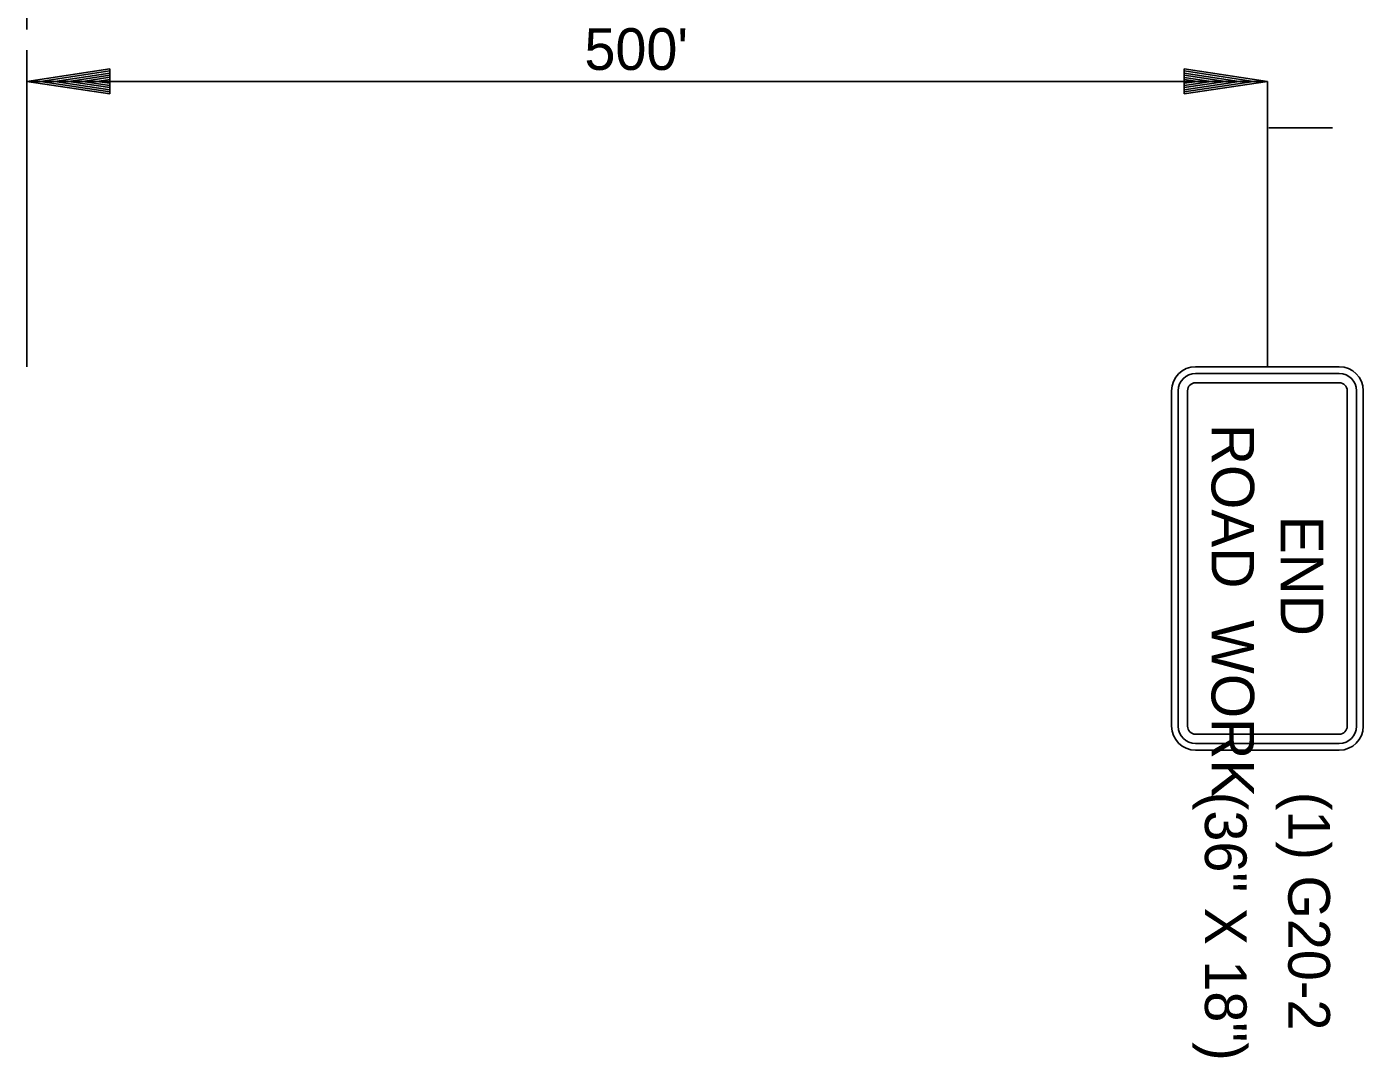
# Model space of a CAD drawing. Extents: x 913 to 1207, y 319 to 519.
# Drawn here: x 1075.27 to 1113.75, y 382.61 to 412.28 of the extents above; entities that cross this region are included whole.
import ezdxf

# ---------------------------------------------------------------- set-up
doc = ezdxf.new("R2010")
doc.units = 0
doc.layers.add('R_Annotation', color=7, linetype='Continuous')
doc.layers.add('R_Draft', color=7, linetype='Continuous')

msp = doc.modelspace()

# ---------------------------------------------------------------- linework, layer by layer
at = {"layer": 'R_Annotation'}
for p, q in [((1113.059, 402.488), (1108.921, 402.488)), ((1113.059, 402.297), (1108.921, 402.297)), ((1108.231, 401.799), (1108.231, 392.142)), ((1108.423, 401.799), (1108.423, 392.142)), ((1108.691, 401.799), (1108.691, 392.142)), ((1113.059, 402.028), (1108.921, 402.028)), ((1113.289, 392.142), (1113.289, 401.799)), ((1113.557, 392.142), (1113.557, 401.799)), ((1113.749, 392.142), (1113.749, 401.799)), ((1108.921, 391.912), (1113.059, 391.912)), ((1108.921, 391.644), (1113.059, 391.644)), ((1108.921, 391.453), (1113.059, 391.453))]:
    msp.add_line(p, q, dxfattribs=at)
for centre, radius, start, end in [((1108.921, 401.799), 0.69, 90, 180), ((1108.921, 401.799), 0.498, 90, 180), ((1113.059, 401.799), 0.69, 360, 90), ((1113.059, 401.799), 0.498, 360, 90), ((1108.921, 401.799), 0.23, 90, 180), ((1113.059, 401.799), 0.23, 360, 90), ((1108.921, 392.142), 0.69, 180, 270), ((1108.921, 392.142), 0.498, 180, 270), ((1108.921, 392.142), 0.23, 180, 270), ((1113.059, 392.142), 0.498, 270, 360), ((1113.059, 392.142), 0.23, 270, 360), ((1113.059, 392.142), 0.69, 270, 360)]:
    msp.add_arc(centre, radius, start, end, dxfattribs=at)
at = {"layer": 'R_Draft'}
for p, q in [((1075.269, 412.194), (1075.269, 419.085)), ((1075.269, 411.602), (1075.269, 402.488)), ((1077.662, 411.062), (1075.269, 410.703)), ((1077.662, 411.002), (1075.668, 410.703)), ((1077.662, 410.344), (1077.662, 411.062)), ((1108.596, 411.062), (1110.99, 410.703)), ((1108.596, 411.062), (1108.596, 410.344)), ((1108.596, 411.002), (1110.59, 410.703)), ((1075.269, 410.703), (1110.99, 410.703)), ((1077.662, 410.344), (1075.269, 410.703)), ((1077.662, 410.404), (1075.668, 410.703)), ((1077.662, 410.941), (1076.08, 410.703)), ((1077.662, 410.464), (1076.08, 410.703)), ((1077.662, 410.881), (1076.479, 410.703)), ((1077.662, 410.524), (1076.479, 410.703)), ((1077.662, 410.82), (1076.884, 410.703)), ((1077.662, 410.587), (1076.884, 410.703)), ((1077.662, 410.759), (1077.284, 410.703)), ((1077.662, 410.647), (1077.284, 410.703)), ((1108.596, 410.941), (1110.178, 410.703)), ((1108.596, 410.881), (1109.78, 410.703)), ((1108.596, 410.819), (1109.374, 410.703)), ((1108.596, 410.759), (1108.974, 410.703)), ((1108.596, 410.344), (1110.99, 410.703)), ((1108.596, 410.586), (1109.374, 410.703)), ((1108.596, 410.464), (1110.178, 410.703)), ((1108.596, 410.404), (1110.59, 410.703)), ((1108.596, 410.524), (1109.78, 410.703)), ((1108.596, 410.647), (1108.974, 410.703)), ((1110.99, 410.703), (1110.99, 408.01)), ((1111.029, 409.363), (1112.867, 409.363)), ((1110.99, 408.01), (1110.99, 402.488))]:
    msp.add_line(p, q, dxfattribs=at)

# ---------------------------------------------------------------- texts
at = {"layer": 'R_Annotation'}
for s, height, p in [('ROAD  WORK', 1.2262, (1109.381, 400.845)), ('END', 1.2262, (1111.373, 398.203)), ('(36" X 18")', 1.2, (1109.19, 390.253)), ('(1) G20-2', 1.2, (1111.59, 390.253))]:
    msp.add_text(s, height=height, rotation=270, dxfattribs=at).set_placement(p)
at = {"layer": 'R_Draft'}
msp.add_text("500'", height=1.2, rotation=360, dxfattribs=at).set_placement((1091.325, 411.033))

doc.saveas('drawing.dxf')
